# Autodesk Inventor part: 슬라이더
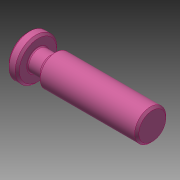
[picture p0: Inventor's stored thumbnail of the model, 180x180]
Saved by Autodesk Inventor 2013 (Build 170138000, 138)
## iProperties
Created: 2016-05
Part Number: 슬라이더
Document SubType Name: Modeling
Designer: mduedu
Density: 7.86 g/cm^3
Material: 강철, 연강
Author: mduedu
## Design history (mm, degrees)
sketch "스케치1"
  geometry: L1 (-7.5, 0)-(52.5, 0); L2 (52.5, 0)-(52.5, 7.5); L3 (52.5, 7.5)-(0, 7.5); L4 (-7.5, 0)-(-7.5, 10); L5 (-7.5, 10)-(-2.5, 10); L6 (-2.5, 10)-(-2.5, 5); L7 (-2.5, 5)-(3.5, 5); L8 (3.5, 5)-(6, 7.5); A1 r 7.5 centre (0, 0) between (0, 7.5) and (-7.5, 0); 1 further point
  constraints: 16 end point, 3 perpendicular, 2 horizontal, 2 parallel, 2 point on circle, 2 point on line, 2 tangent, 1 centre point, 1 coincident
  dimensions: "d0" = 15 diameter of A1; "d1" = 60 distance of L1.start L1.end; "d19" = 20 diameter of L5 L1; "d20" = 10 diameter of L7 L1; "d21" = 5 distance of L4.end L5.end; "d22" = 135 deg angle of L8 L7; "d23" = 6 distance of L6.end L7.end
revolve "회전1" stored, may be unused: angle "d4" = 90 deg
chamfer "모따기2" distance "d24" = 1; stored, may be unused: second distance "d25" = 2, angle "d26" = 45 deg
fillet "모깎기1" dims "d27" = 0.5
node "솔리드1"
